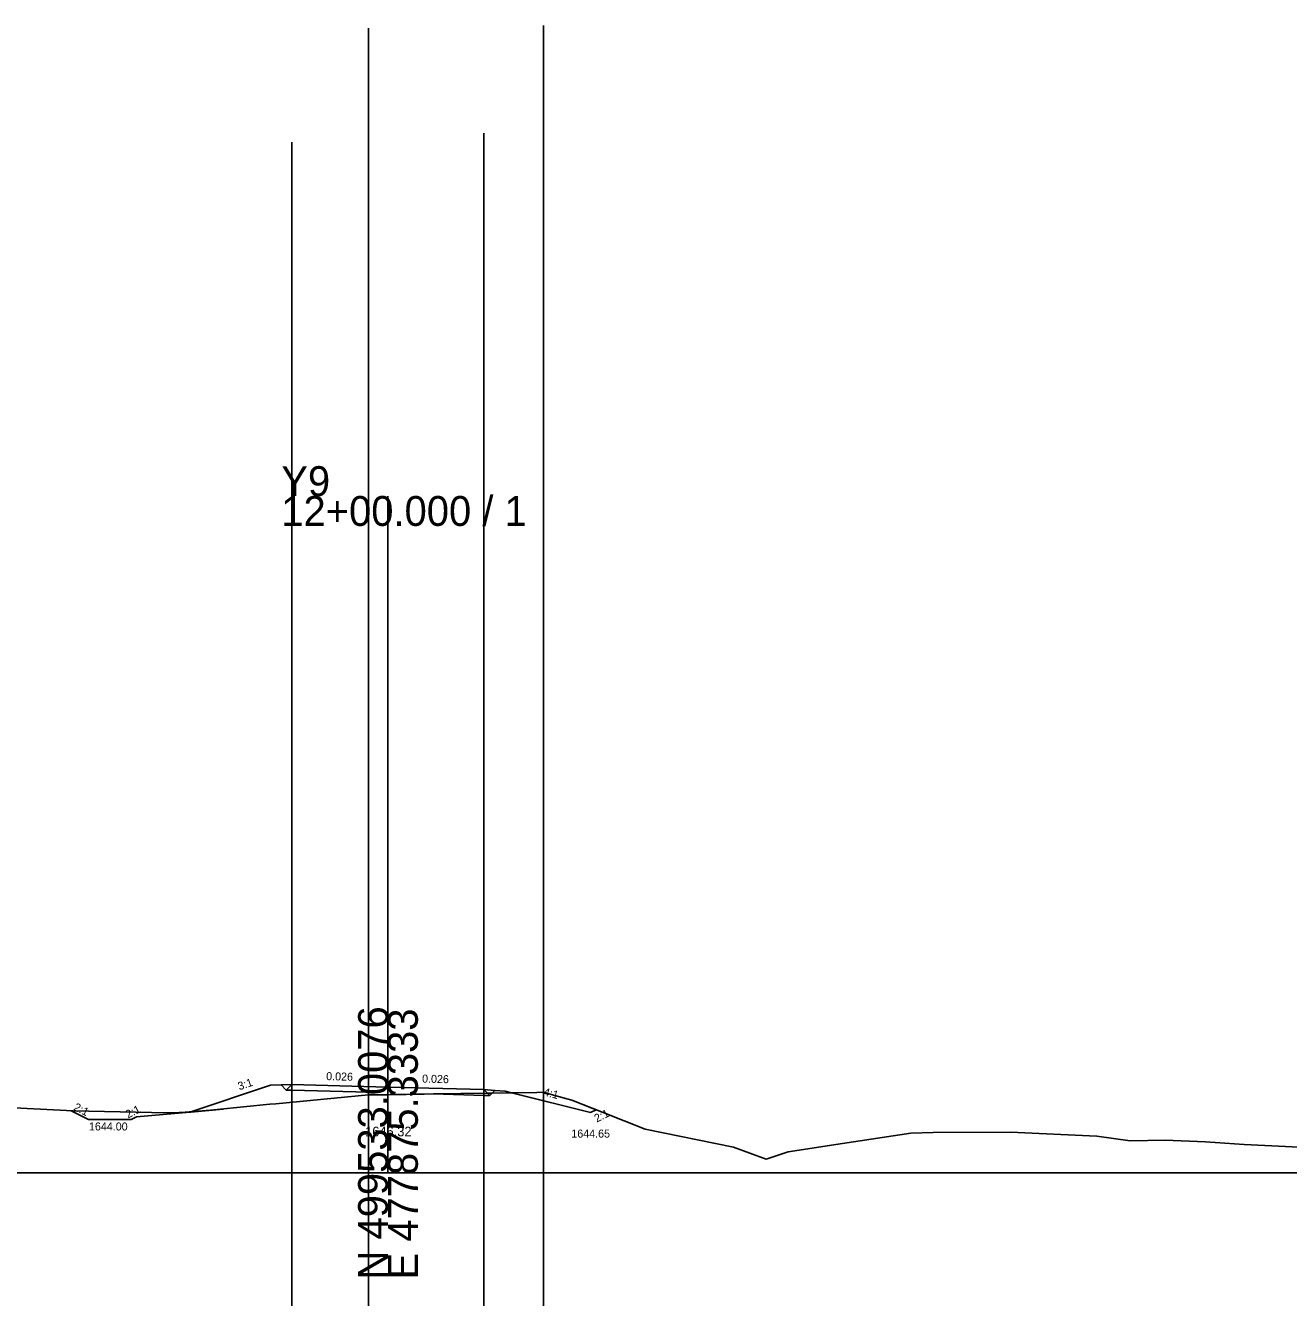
# Model space of a CAD drawing. Extents: x -26 to 403, y -99 to 4540.
# Drawn here: x 166 to 284.4, y 1988.3 to 2107.6 of the extents above; entities that cross this region are included whole.
import ezdxf

# ---------------------------------------------------------------- set-up
doc = ezdxf.new("R2010")
doc.units = 0
for name, color, linetype in [('Exist Cross Section Cell', 7, 'Continuous'), ('Exist XS Center Line Elevation Label', 7, 'Continuous'), ('Exist XS Ground Line', 7, 'Continuous'), ('Prop XS DDE', 7, 'Continuous'), ('Prop XS DDE Earthwork Shape', 7, 'Continuous'), ('Prop XS Ditch Slope Text', 7, 'Continuous'), ('Prop XS Ditch Standard Text', 7, 'Continuous'), ('Prop XS Dump Level', 7, 'Continuous'), ('Prop XS Earthwork Shape', 7, 'Continuous'), ('Prop XS EOT Tick Mark', 7, 'Continuous'), ('Prop XS Finish Grade', 7, 'Continuous'), ('Prop XS Finish Grade Earthwork', 7, 'Continuous'), ('Prop XS Finish Grade Pavement', 7, 'Continuous'), ('Prop XS Hydro Typical Ditch Data', 7, 'Continuous'), ('Prop XS Pvmt Edge Slope', 7, 'Continuous'), ('Prop XS SE Text', 7, 'Continuous'), ('Prop XS Shoulder Borrow Shape', 7, 'Continuous'), ('Prop XS Side Slope Text', 7, 'Continuous'), ('Prop XS Subgrade Earthwork', 7, 'Continuous'), ('Scratch_Level_1', 7, 'Continuous'), ('Scratch_Level_6', 7, 'Continuous')]:
    doc.layers.add(name, color=color, linetype=linetype)

msp = doc.modelspace()

# ---------------------------------------------------------------- linework, layer by layer
at = {"layer": 'Exist Cross Section Cell'}
for p, q in [((200, 2000), (200, 2063.44)), ((0, 2000), (200, 2000)), ((200, 2000), (400, 2000))]:
    msp.add_line(p, q, dxfattribs=at)
at = {"layer": 'Exist XS Ground Line'}
msp.add_lwpolyline([(163.07, 2006.17), (170.48, 2005.8), (179.31, 2005.62), (181.51, 2005.67), (188.94, 2006.43), (189.5, 2006.48), (198.16, 2007.3), (198.73, 2007.31), (200, 2007.32), (206.82, 2007.43), (213.96, 2007.53), (214.58, 2007.56), (215.31, 2007.35), (217.24, 2006.8), (220.16, 2005.66), (224.11, 2004.1), (232.38, 2002.41), (235.46, 2001.29), (237.53, 2001.95), (242.62, 2002.75), (249.01, 2003.73), (251.11, 2003.77), (258.35, 2003.81), (266.45, 2003.44), (269.58, 2003.01), (272.86, 2003.05), (276.65, 2002.9), (280.26, 2002.65), (287.37, 2002.31)], dxfattribs=at)
at = {"layer": 'Prop XS DDE'}
for p, q in [((170.3, 2005.81), (171.92, 2005)), ((175.92, 2005), (171.92, 2005)), ((175.92, 2005), (176.43, 2005.25)), ((176.43, 2005.25), (181.43, 2005.67))]:
    msp.add_line(p, q, dxfattribs=at)
at = {"layer": 'Prop XS DDE Earthwork Shape'}
for p, q in [((170.3, 2005.81), (171.92, 2005)), ((171.92, 2005), (175.92, 2005)), ((175.92, 2005), (176.43, 2005.25)), ((176.43, 2005.25), (181.43, 2005.67)), ((181.43, 2005.67), (180.57, 2005.65))]:
    msp.add_line(p, q, dxfattribs=at)
msp.add_lwpolyline([(181.51, 2005.67), (184.55, 2005.98), (180.57, 2005.65)], close=True, dxfattribs=at)
msp.add_lwpolyline([(181.51, 2005.67), (184.55, 2005.98), (180.57, 2005.65)], close=True, dxfattribs=at)
msp.add_lwpolyline([(181.51, 2005.67), (184.55, 2005.98), (180.57, 2005.65)], close=True, dxfattribs=at)
msp.add_lwpolyline([(180.57, 2005.65), (179.31, 2005.62), (170.48, 2005.8), (170.3, 2005.81)], dxfattribs=at)
at = {"layer": 'Prop XS Dump Level'}
for p, q in [((191, 2008.28), (200, 2008.04)), ((200, 2008.04), (208.99, 2007.81))]:
    msp.add_line(p, q, dxfattribs=at)
at = {"layer": 'Prop XS Earthwork Shape'}
for points in [[(198.16, 2007.55), (191, 2007.74), (190.47, 2007.75), (189.98, 2008.24), (189, 2008.21), (181.43, 2005.67), (181.51, 2005.67), (188.94, 2006.43), (189.5, 2006.48), (198.16, 2007.3)], [(206.82, 2007.43), (209.77, 2007.47), (209.55, 2007.25), (208.99, 2007.26), (204.26, 2007.39)], [(210.02, 2007.72), (210.99, 2007.65), (211.59, 2007.5), (209.77, 2007.47)], [(215.31, 2007.35), (217.24, 2006.8), (219.52, 2005.91), (218.99, 2005.65), (211.59, 2007.5), (213.96, 2007.53), (214.58, 2007.56)]]:
    msp.add_lwpolyline(points, close=True, dxfattribs=at)
at = {"layer": 'Prop XS EOT Tick Mark'}
for p, q in [((191, 2008.28), (191, 2009.28)), ((208.99, 2007.81), (208.99, 2008.81))]:
    msp.add_line(p, q, dxfattribs=at)
at = {"layer": 'Prop XS Finish Grade'}
for p, q in [((191, 2008.28), (189.98, 2008.24)), ((208.99, 2007.81), (210.02, 2007.72))]:
    msp.add_line(p, q, dxfattribs=at)
at = {"layer": 'Prop XS Finish Grade Earthwork'}
for p, q in [((189, 2008.21), (181.43, 2005.67)), ((189.98, 2008.24), (189, 2008.21)), ((210.02, 2007.72), (210.99, 2007.65)), ((210.99, 2007.65), (218.99, 2005.65)), ((218.99, 2005.65), (219.52, 2005.91))]:
    msp.add_line(p, q, dxfattribs=at)
at = {"layer": 'Prop XS Finish Grade Pavement'}
for p, q in [((191, 2008.28), (200, 2008.04)), ((200, 2008.04), (208.99, 2007.81))]:
    msp.add_line(p, q, dxfattribs=at)
at = {"layer": 'Prop XS Hydro Typical Ditch Data'}
for p, q in [((210.99, 2007.65), (218.99, 2005.65)), ((218.99, 2005.65), (219.52, 2005.91))]:
    msp.add_line(p, q, dxfattribs=at)
at = {"layer": 'Prop XS Pvmt Edge Slope'}
for p, q in [((191, 2008.28), (190.47, 2007.75)), ((208.99, 2007.81), (209.55, 2007.25))]:
    msp.add_line(p, q, dxfattribs=at)
at = {"layer": 'Prop XS Shoulder Borrow Shape'}
for points in [[(191, 2008.28), (189.98, 2008.24), (190.47, 2007.75)], [(208.99, 2007.81), (210.02, 2007.72), (209.55, 2007.25)]]:
    msp.add_lwpolyline(points, close=True, dxfattribs=at)
at = {"layer": 'Prop XS Subgrade Earthwork'}
for p, q in [((190.47, 2007.75), (189.98, 2008.24)), ((191, 2007.74), (190.47, 2007.75)), ((198.16, 2007.55), (191, 2007.74)), ((198.16, 2007.55), (198.16, 2007.3)), ((208.99, 2007.26), (204.26, 2007.39)), ((208.99, 2007.26), (209.55, 2007.25)), ((209.55, 2007.25), (210.02, 2007.72))]:
    msp.add_line(p, q, dxfattribs=at)
at = {"layer": 'Scratch_Level_1'}
for p, q in [((198.16, 2107.3), (198.16, 1907.3)), ((214.58, 2107.56), (214.58, 1907.56))]:
    msp.add_line(p, q, dxfattribs=at)
at = {"layer": 'Scratch_Level_6'}
for p, q in [((191, 2096.63), (191, 1946.63)), ((209, 2097.46), (209, 1947.46)), ((198.16, 2007.3), (204.26, 2007.39))]:
    msp.add_line(p, q, dxfattribs=at)

# ---------------------------------------------------------------- texts
at = {"layer": 'Exist Cross Section Cell'}
for s, p in [('Y9', (190, 2063.44)), ('12+00.000 / 1', (190, 2060.64))]:
    msp.add_text(s, height=2.8, dxfattribs=at).set_placement(p)
for s, p in [('N 499533.0076', (200, 1990)), ('E 477875.3333', (202.8, 1990))]:
    msp.add_text(s, height=2.8, rotation=90, dxfattribs=at).set_placement(p)
at = {"layer": 'Exist XS Center Line Elevation Label'}
msp.add_text('1646.32', height=0.9, dxfattribs=at).set_placement((197.86, 2003.42))
at = {"layer": 'Prop XS Ditch Slope Text'}
msp.add_text('4:1', height=0.75, rotation=345.9638, dxfattribs=at).set_placement((214.53, 2007.25))
at = {"layer": 'Prop XS Ditch Standard Text'}
for s, p in [('1644.00', (171.97, 2003.97)), ('1644.65', (217.19, 2003.3))]:
    msp.add_text(s, height=0.75, dxfattribs=at).set_placement(p)
at = {"layer": 'Prop XS Dump Level'}
for p in [(189, 2008.17), (210.99, 2007.61)]:
    msp.add_text('Case1', height=0.04, dxfattribs=at).set_placement(p)
at = {"layer": 'Prop XS SE Text'}
for p in [(194.2, 2008.69), (203.19, 2008.46)]:
    msp.add_text('0.026', height=0.75, rotation=358.5, dxfattribs=at).set_placement(p)
at = {"layer": 'Prop XS Side Slope Text'}
for s, rotation, p in [('3:1', 18.5386, (186.07, 2007.73)), ('2:1', 333.416, (170.47, 2005.92)), ('2:1', 26.5651, (175.63, 2005.09)), ('2:1', 26.565, (219.57, 2004.71))]:
    msp.add_text(s, height=0.75, rotation=rotation, dxfattribs=at).set_placement(p)

doc.saveas('drawing.dxf')
